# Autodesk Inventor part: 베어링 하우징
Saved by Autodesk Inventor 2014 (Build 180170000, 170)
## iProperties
Created: 2026-05
Part Number: 베어링 하우징
Material: 알루미늄 6061
Document SubType Name: Modeling
Designer: dg
Density: 2.71 g/cm^3
Appearance: 알루미늄 - 평지
Mass: 507.225 g
Surface Area: 428.264 cm^2
Volume: 187.168 cm^3
Author: jhkim
Creation Date: 2026-04-23
Sending System: Autodesk Inventor 2027
Preprocessor: ST-DEVELOPER v20.1
Author: dg
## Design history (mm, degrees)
node "베어링 하우징1"
node "솔리드1"
node "기준1"
